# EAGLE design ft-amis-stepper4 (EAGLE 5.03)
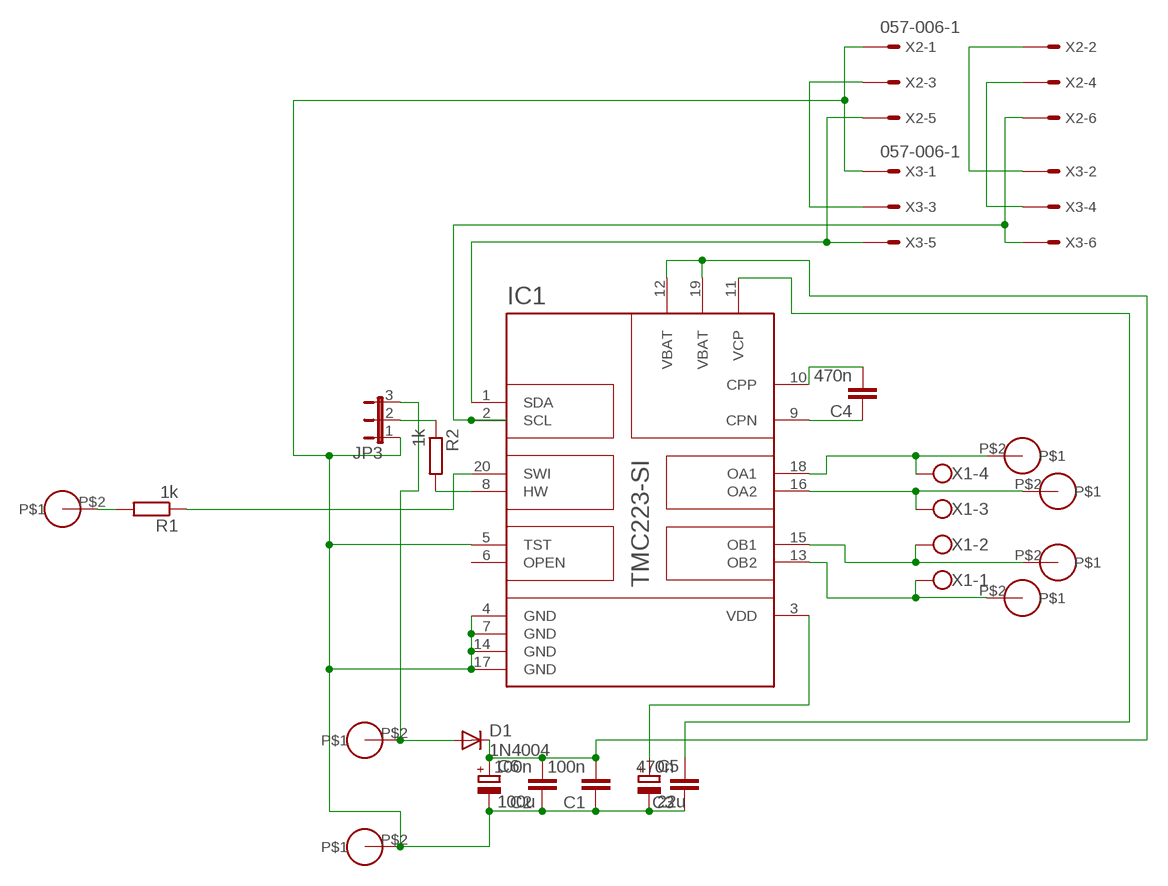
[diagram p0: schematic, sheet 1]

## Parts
C1  100n  C-EUC0805  [C0805]
C2  100n  C-EUC0805  [C0805]
C3  470n  C-EUC2012  [C2012]
C4  470n  C-EUC2012  [C2012]
C5  22u  CPOL-EUCT7343  [CT7343]
C6  100u  CPOL-EUTT2D7L  [TT2D7L]
D1  1N4004  [DO41-10]
IC1  TMC223-SI  [SOIC20]
JP3  JP2E  [JP2]
R1  1k  R-EU_R0805  [R0805]
R2  1k  R-EU_R0805  [R0805]
U$2  STEKKERBUS2_5  [STEKKERBUS2_5]
U$3  STEKKERBUS2_5  [STEKKERBUS2_5]
U$4  STEKKERBUS2_5  [STEKKERBUS2_5]
U$6  STEKKERBUS2_5  [STEKKERBUS2_5]
U$7  STEKKERBUS2_5  [STEKKERBUS2_5]
U$8  STEKKERBUS2_5  [STEKKERBUS2_5]
U$9  STEKKERBUS2_5  [STEKKERBUS2_5]
X1  W237-04P  [W237-4P]
X2  057-006-1  [057-006-1]
X3  057-006-1  [057-006-1]

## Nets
N$1: JP3.2 R2.1
N$2: R1.2 U$4.P$2
N$3: C1.2 C2.2 C6.+ D1.C IC1.12(VBAT) IC1.19(VBAT)
N$5: C5.+ IC1.3(VDD)
N$6: C3.2 IC1.11(VCP)
N$7: IC1.20(SWI) R1.1
N$8: IC1.18(OA1) U$6.P$2 X1.4
N$9: IC1.16(OA2) U$7.P$2 X1.3
N$10: IC1.15(OB1) U$8.P$2 X1.2
N$11: IC1.13(OB2) U$9.P$2 X1.1
N$12: C1.1 C2.1 C3.1 C5.- C6.- IC1.4(GND) IC1.5(TST) IC1.7(GND) IC1.14(GND) IC1.17(GND) JP3.1 U$3.P$2 X2.1 X3.1
N$13: D1.A JP3.3 U$2.P$2
N$14: C4.2 IC1.10(CPP)
N$15: C4.1 IC1.9(CPN)
N$16: IC1.1(SDA) X2.5 X3.5
N$17: X2.4 X3.4
N$18: IC1.2(SCL) X2.6 X3.6
N$20: X2.3 X3.3
N$21: X2.2 X3.2
N$23: IC1.8(HW) R2.2
Unconnected: IC1.6(OPEN)

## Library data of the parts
C1-C4 = rcl:C-EU: CAPACITOR, European symbol
C5 C6 = rcl:CPOL-EU: POLARIZED CAPACITOR, European symbol
D1 = diode:1N4004: DIODE
IC1 = trinamic-2:TMC223-SI: TRINAMIC Micro Stepping Stepper Motor Controller / Driver with Two Wire Serial Interface and Sensorless Stall Detection Information given in this library is believed to be accurate and reliable. However no warranty is given for its correctness. Datasheet for TMC223 Description Micro Stepping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
JP3 = jumper:JP2E: JUMPER
R1 R2 = rcl:R-EU_: RESISTOR, European symbol
U$2-U$4 U$6-U$9 = myown:STEKKERBUS2_5
X1 = con-wago-508:W237-04P: WAGO SREW CLAMP
X2 X3 = con-panduit:057-006-: CONNECTOR 6-pin series 057 contact pc board low profile headers

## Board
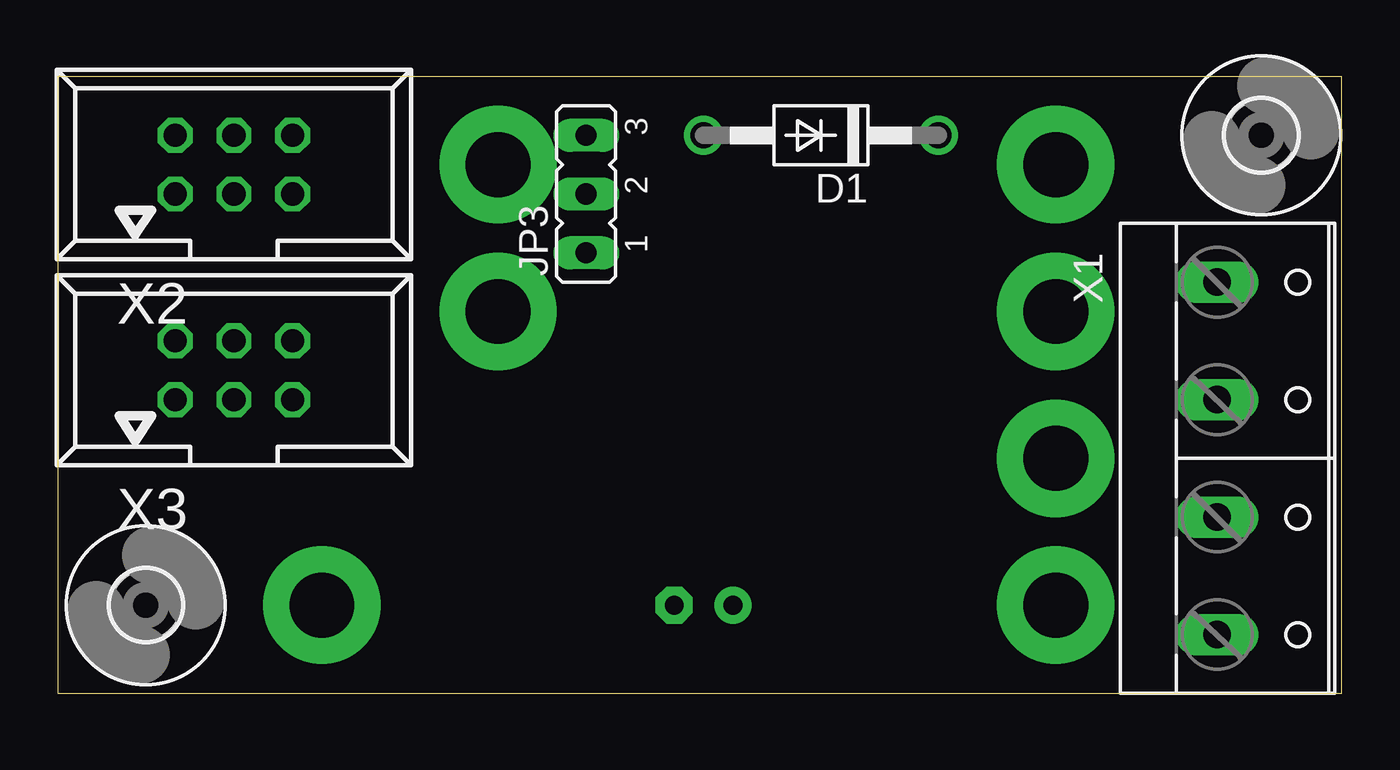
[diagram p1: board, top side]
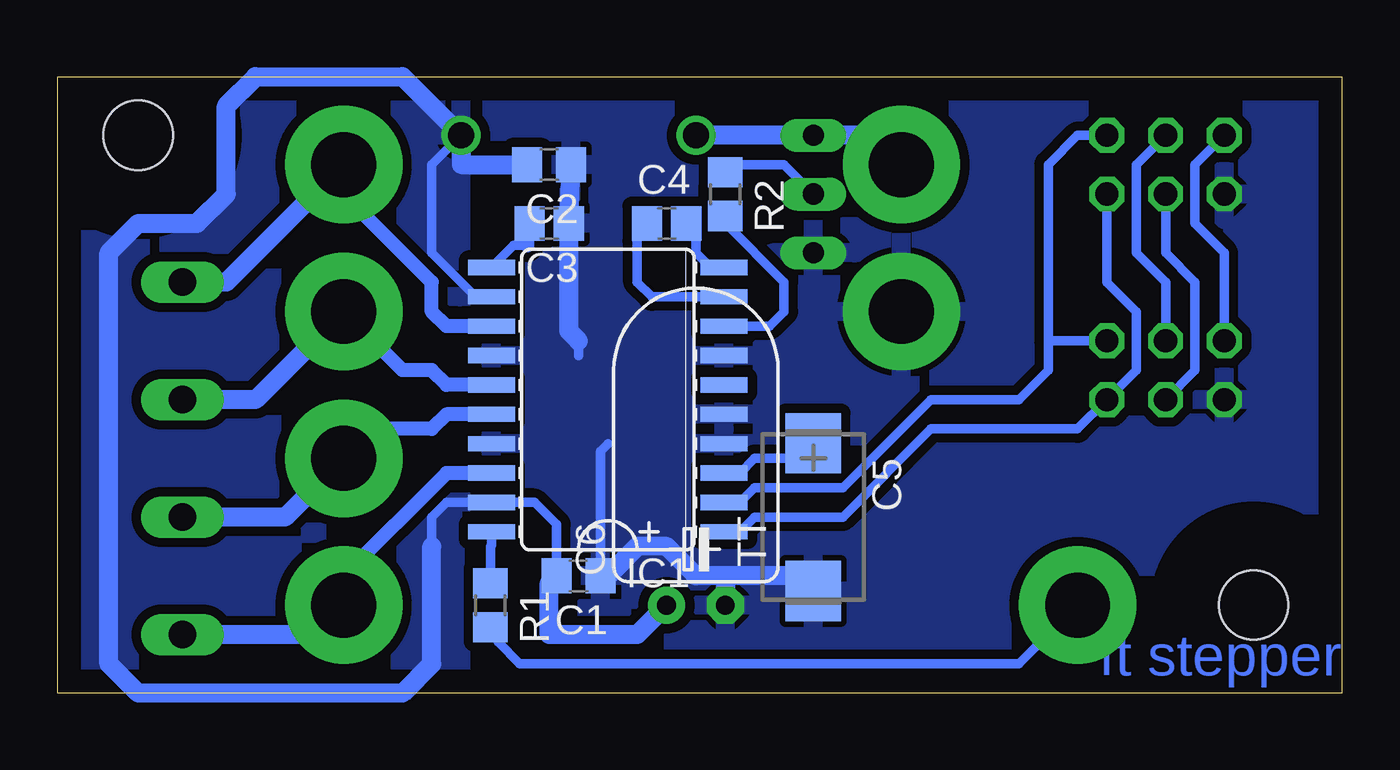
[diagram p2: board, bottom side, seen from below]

Size 55.55 x 26.66 mm. Coordinates in mm from the lower left corner, seen from the top.
Outline: 0,0 55.55,0 55.55,26.66 0,26.66 0,0
Copper layers (1*16): Top 0.035mm / dielectric 1.5mm / Bottom 0.035mm
Design rules "default": minimum track width 10mil, minimum drill 24mil, track to track 8mil, track to pad 8mil, pad to pad 8mil, via to via 8mil, smd to smd 8mil, copper to edge 40mil, drill to drill 8mil, minimum pad ring 10mil, minimum via ring 8mil, stop-mask expansion 4mil, vias tented up to drill 0mil, thermal gap 10mil

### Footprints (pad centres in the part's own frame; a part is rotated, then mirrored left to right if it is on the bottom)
C0805 = smd 1.3 x 1.5: 1 -0.95,0; 2 0.95,0
C2012 = smd 1.3 x 1.5: 1 -0.85,0; 2 0.85,0
CT7343 = smd 2.6 x 2.4: + -3.2,0; - 3.2,0
TT2D7L = drill 0.813 pad 1.6 round: + -1.27,0 | drill 0.813 pad 1.6 octagon: - 1.27,0
DO41-10 = drill 1.118 round: A 5.08,0; C -5.08,0
SOIC20 = smd 2.032 x 0.66: 1 -5.029,5.715; 2 -5.029,4.445; 3 -5.029,3.175; 4 -5.029,1.905; 5 -5.029,0.635; 6 -5.029,-0.635; 7 -5.029,-1.905; 8 -5.029,-3.175; 9 -5.029,-4.445; 10 -5.029,-5.715; 11 5.029,-5.715; 12 5.029,-4.445; 13 5.029,-3.175; 14 5.029,-1.905; 15 5.029,-0.635; 16 5.029,0.635; 17 5.029,1.905; 18 5.029,3.175; 19 5.029,4.445; 20 5.029,5.715
JP2 = drill 0.914 long: 1 -2.54,0; 2 0,0; 3 2.54,0
R0805 = smd 1.3 x 1.5: 1 -0.95,0; 2 0.95,0
STEKKERBUS2_5 = drill 2.8 pad 5.08 round: P$2 0,0
3,0 = hole 3: 0,0
W237-4P = drill 1.194 long: 1 -7.62,-0.635; 2 -2.54,-0.635; 3 2.54,-0.635; 4 7.62,-0.635
057-006-1 = drill 1 octagon: 1 -2.54,-1.27; 2 -2.54,1.27; 3 0,-1.27; 4 0,1.27; 5 2.54,-1.27; 6 2.54,1.27

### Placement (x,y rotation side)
C1  33.02,5.08 180 bottom
C2  34.29,22.86 180 bottom
C3  34.29,20.32 180 bottom
C4  29.21,20.32 0 bottom
C5  22.86,7.62 270 bottom
C6  27.94,3.81 0 bottom
D1  33.02,24.13 180 top
IC1  31.75,12.7 180 bottom
JP3  22.86,21.59 90 top
R1  36.83,3.81 270 bottom
R2  26.67,21.59 270 bottom
U$2  19.05,22.86 0 top
U$3  19.05,16.51 0 top
U$4  11.43,3.81 0 top
U$5  [3,0]  52.07,24.13 0 top
U$6  43.18,3.81 0 top
U$7  43.18,10.16 0 top
U$8  43.18,16.51 0 top
U$9  43.18,22.86 0 top
U$10  [3,0]  3.81,3.81 0 top
X1  50.8,10.16 270 top
X2  7.62,22.86 0 top
X3  7.62,13.97 0 top

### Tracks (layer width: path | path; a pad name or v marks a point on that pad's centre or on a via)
N$1
  Bottom 0.406: JP3.2 24.13,22.86 26.35,22.86 R2.1
N$2
  Bottom 0.406: R1.2 36.51,2.54 36.51,2.22 35.56,1.27 13.97,1.27 U$4.P$2
N$3
  Bottom 0.406: C1.2 33.97,7.3 34.92,8.26 IC1.19 38.73,8.26 39.37,7.62 39.37,1.27 | IC1.12 37.47,17.14 39.37,19.05 39.37,22.86 D1.C
  Bottom 0.813: C1.2 34.29,4.76 34.29,2.54 30.48,2.54 C6.+ | 39.37,6.35 39.37,1.27 40.64,0 52.07,0 53.34,1.27 53.34,19.05 52.07,20.32 49.53,20.32 48.26,21.59 48.26,25.4 46.99,26.67 40.64,26.67 D1.C 38.1,22.86 C2.2
  pour Bottom (isolate 0.406): 38.1,24.13 38.1,26.67 55.88,26.67 55.88,0 38.1,0
N$5
  Bottom 0.406: C5.+ 23.52,10.16 25.4,10.16 26.04,9.53 IC1.3
N$6
  Bottom 0.406: 35.24,19.37 35.82,19.37 IC1.11
  Bottom 0.61: 35.24,19.37 C3.2
N$7
  Bottom 0.406: R1.1 36.83,6.35 36.78,6.4 IC1.20
N$8
  Bottom 0.61: U$6.P$2 43.18,5.08 38.73,9.53 IC1.18
  Bottom 0.813: X1.4 44.45,2.54 U$6.P$2
N$9
  Bottom 0.61: U$7.P$2 41.91,11.43 39.37,11.43 38.73,12.06 IC1.16
  Bottom 0.813: X1.3 45.72,7.62 U$7.P$2
N$10
  Bottom 0.61: U$8.P$2 40.64,13.97 39.37,13.97 38.73,13.34 IC1.15
  Bottom 0.813: X1.2 46.99,12.7 U$8.P$2
N$11
  Bottom 0.61: IC1.13 38.73,15.88 39.37,16.51 39.37,17.78 43.18,21.59 U$9.P$2
  Bottom 0.813: X1.1 48.26,17.78 U$9.P$2
N$12
  Bottom 0.406: 33.02,14.61 33.02,15.24 | C1.1 32.07,10.47 31.75,10.79 | 33.39,21.61 33.38,21.59
  Bottom 0.813: C2.1 33.39,21.61 C3.1 33.44,15.66 33.02,15.24 | 26.67,5.08 C6.- | 26.67,5.08 22.86,5.08 C5.- | 26.67,5.08 27.94,5.08 29.21,6.35 30.48,6.35 31.75,5.08
  pour Bottom (isolate 0.406): 2.54,25.4 2.54,26.67 36.83,26.67 36.83,0 0,0 0,25.4
N$13
  Bottom 0.813: U$2.P$2 20.32,24.13 JP3.3 | JP3.3 D1.A JP3.3
N$14
  Bottom 0.406: IC1.10 27.3,18.41 27.94,19.05 27.94,19.9 C4.2
N$15
  Bottom 0.406: IC1.9 29.84,17.14 30.48,17.78 30.48,19.9 C4.1
N$16
  Bottom 0.406: X2.5 10.16,17.78 8.89,16.51 8.89,13.97 X3.5 11.43,11.43 17.78,11.43 21.59,7.62 25.4,7.62 26.04,6.99 IC1.1
N$17
  Bottom 0.406: X2.4 8.89,22.86 8.89,19.05 7.62,17.78 X3.4
N$18
  Bottom 0.406: X2.6 11.43,24.13 12.7,22.86 12.7,15.24 | 12.7,15.24 12.7,13.97 13.97,12.7 17.78,12.7 21.59,8.89 25.4,8.89 26.04,8.26 IC1.2 | X3.6 12.7,15.24
N$20
  Bottom 0.406: X3.3 6.35,13.97 6.35,17.78 7.62,19.05 X2.3
N$21
  Bottom 0.406: X3.2 5.08,19.05 6.35,20.32 6.35,22.86 X2.2
N$23
  Bottom 0.406: R2.2 26.67,20.32 24.13,17.78 24.13,16.51 24.77,15.88 IC1.8

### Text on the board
Bottom: ft stepper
